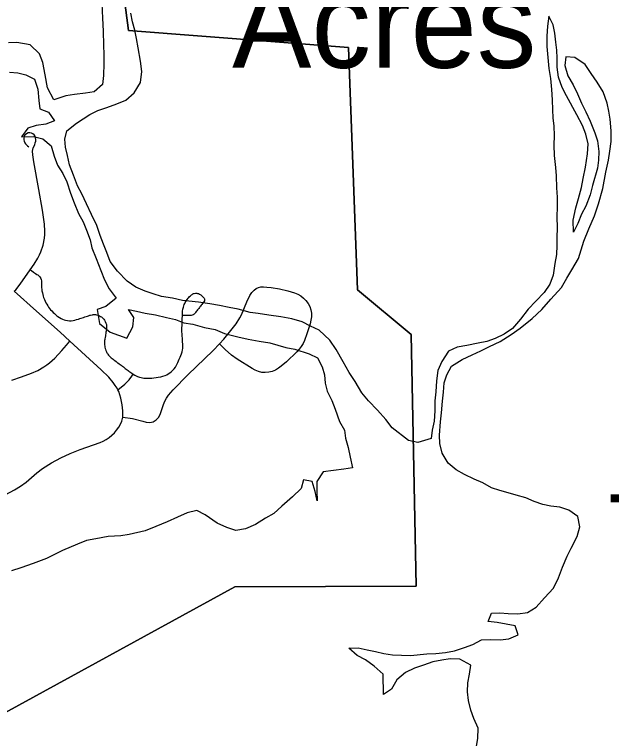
# Model space of a CAD drawing. Extents: x 63.4 to 97.4, y 0.4 to 22.4.
# Drawn here: x 68.856 to 69.385, y 18.029 to 18.671 of the extents above; entities that cross this region are included whole.
import ezdxf

# ---------------------------------------------------------------- set-up
doc = ezdxf.new("R2010")
doc.units = 0
for name, color, linetype in [('GM_X_County_Road', 7, 'Continuous'), ('GM_X_Minor_River', 7, 'Continuous'), ('GM_X_Township_Road', 7, 'Continuous'), ('GM_X_Township_Road_Text', 7, 'Continuous'), ('GM_X_Unincorporated_Text', 7, 'Continuous')]:
    doc.layers.add(name, color=color, linetype=linetype)

msp = doc.modelspace()

# ---------------------------------------------------------------- linework, layer by layer
at = {"layer": 'GM_X_County_Road'}
for points in [[(68.14823, 17.66929), (69.05133, 18.16366), (69.21209, 18.16431), (69.20756, 18.38738), (69.1601, 18.4272), (69.15215, 18.64192), (68.95685, 18.65711), (68.94039, 18.78359), (68.93181, 18.90191), (69.43522, 19.41404), (69.59166, 19.50401), (69.66099, 19.53265), (69.65817, 19.63452), (69.8362, 19.73783), (69.85096, 19.75421), (69.8604, 19.7797), (69.89905, 20.06449)], [(69.89905, 20.06449), (69.8604, 19.7797), (69.85096, 19.75421), (69.8362, 19.73783), (69.65817, 19.63452), (69.66099, 19.53265), (69.59166, 19.50401), (69.43522, 19.41404), (68.93181, 18.90191), (68.94039, 18.78359), (68.95685, 18.65711), (69.15215, 18.64192), (69.1601, 18.4272), (69.20756, 18.38738), (69.21209, 18.16431), (69.05133, 18.16366), (68.14823, 17.66929)]]:
    msp.add_lwpolyline(points, dxfattribs=at)
at = {"layer": 'GM_X_Minor_River'}
for points in [[(68.93307, 18.68111), (68.93389, 18.66819), (68.93433, 18.6564), (68.93477, 18.64424), (68.93482, 18.63587), (68.93486, 18.62789), (68.93453, 18.61724), (68.93381, 18.60925), (68.92626, 18.60275), (68.91867, 18.60158), (68.9088, 18.60039), (68.90122, 18.59921), (68.8906, 18.59574), (68.88485, 18.60636), (68.8829, 18.61776), (68.88094, 18.62877), (68.87787, 18.63636), (68.86947, 18.64431), (68.85769, 18.64653), (68.85048, 18.64612)], [(68.95439, 18.59528), (68.96195, 18.60178), (68.9676, 18.61093), (68.96868, 18.62083), (68.9675, 18.62994), (68.96554, 18.64172), (68.96398, 18.65008), (68.96242, 18.65729), (68.96048, 18.66489), (68.95893, 18.67249)], [(69.35725, 18.21702), (69.35568, 18.22614), (69.34768, 18.2318), (69.33969, 18.23443), (69.33172, 18.23515), (69.3245, 18.23664), (69.31689, 18.23926), (69.30928, 18.24265), (69.30092, 18.24489), (69.29369, 18.24713), (69.28647, 18.249), (69.27886, 18.25162), (69.27125, 18.25577), (69.26364, 18.25916), (69.25488, 18.2633), (69.24765, 18.26744), (69.2404, 18.27349), (69.23504, 18.28221), (69.2331, 18.29094), (69.23269, 18.29817), (69.23376, 18.30996), (69.23448, 18.31794), (69.23557, 18.32821), (69.23629, 18.3362), (69.237, 18.34457), (69.23924, 18.3518), (69.24338, 18.35942), (69.25284, 18.36517), (69.26193, 18.3694), (69.26951, 18.37285), (69.27708, 18.37669), (69.28655, 18.3813), (69.29639, 18.38743), (69.30433, 18.39317), (69.31492, 18.40158), (69.32361, 18.40961), (69.33154, 18.41877), (69.34098, 18.42908), (69.34587, 18.43747), (69.35039, 18.44471), (69.35603, 18.455), (69.36089, 18.47023), (69.36539, 18.48128), (69.37026, 18.49271), (69.37401, 18.50337), (69.37773, 18.51707), (69.38031, 18.53153), (69.38292, 18.54219), (69.38402, 18.55018), (69.38511, 18.55855), (69.38506, 18.56805), (69.38425, 18.57832), (69.38308, 18.58553), (69.38152, 18.59275), (69.37805, 18.60262), (69.37269, 18.61134), (69.36734, 18.61892), (69.36198, 18.62687), (69.35284, 18.6333), (69.34486, 18.63364), (69.34414, 18.62603), (69.34684, 18.61692), (69.35144, 18.60896), (69.35528, 18.60099), (69.35874, 18.59264), (69.36258, 18.58505), (69.36641, 18.57671), (69.37064, 18.56646), (69.37296, 18.55925), (69.37415, 18.54975), (69.37381, 18.54215), (69.37308, 18.53492), (69.36861, 18.51969), (69.36637, 18.51132), (69.36263, 18.50141), (69.35887, 18.49417), (69.35549, 18.48579), (69.35173, 18.47817), (69.3513, 18.48882), (69.3539, 18.49985), (69.35614, 18.50823), (69.35874, 18.51774), (69.36022, 18.52573), (69.36245, 18.53601), (69.36429, 18.5478), (69.36462, 18.55655), (69.36268, 18.56529), (69.3596, 18.57288), (69.35462, 18.58236), (69.34542, 18.59904), (69.34158, 18.60663), (69.3385, 18.61574), (69.33731, 18.62448), (69.33727, 18.63246), (69.33686, 18.63968), (69.33606, 18.6469), (69.33526, 18.65488), (69.3337, 18.6621), (69.32987, 18.66968), (69.32877, 18.66093), (69.32806, 18.65219)], [(69.32806, 18.65219), (69.32811, 18.64306), (69.32892, 18.63318), (69.32973, 18.6233), (69.33129, 18.61456), (69.3321, 18.60468), (69.33291, 18.59556), (69.33295, 18.58682), (69.33337, 18.57959), (69.33417, 18.57237), (69.33459, 18.56401), (69.33425, 18.55527), (69.33468, 18.54614), (69.33588, 18.53551), (69.33629, 18.52828), (69.33672, 18.51764), (69.33715, 18.50928), (69.33719, 18.50053), (69.33686, 18.49217), (69.33729, 18.48191), (69.33695, 18.47392), (69.33699, 18.46632), (69.33665, 18.45833), (69.33517, 18.45034), (69.33371, 18.44007), (69.33071, 18.43207), (69.32581, 18.42482), (69.31826, 18.41718), (69.31146, 18.40993), (69.30467, 18.40115), (69.2975, 18.39276), (69.29031, 18.38778), (69.28236, 18.38394), (69.27478, 18.38124), (69.2672, 18.37969), (69.25695, 18.37773), (69.24861, 18.37618), (69.24066, 18.37272), (69.23501, 18.36357), (69.23125, 18.35556), (69.23016, 18.34643), (69.22945, 18.33655), (69.22873, 18.32856), (69.22878, 18.31982), (69.22806, 18.31069), (69.22621, 18.3027), (69.22548, 18.29509), (69.21373, 18.29161), (69.20537, 18.29348), (69.19089, 18.30481), (69.18516, 18.31201), (69.1779, 18.32034), (69.16988, 18.32866), (69.16377, 18.33586), (69.15803, 18.34571), (69.15267, 18.35367), (69.14731, 18.36315), (69.14118, 18.37415), (69.13544, 18.38248), (69.1259, 18.39118), (69.11829, 18.39495), (69.11106, 18.39871), (69.10193, 18.40133), (69.09205, 18.40319), (69.08141, 18.40466), (69.07191, 18.40613), (69.0647, 18.40686), (69.05405, 18.40985), (69.04607, 18.41133), (69.03771, 18.41319), (69.02897, 18.41467), (69.01909, 18.41614), (69.00466, 18.4176), (68.99591, 18.41984), (68.98603, 18.42131), (68.97881, 18.42356), (68.97158, 18.4258), (68.96321, 18.42956), (68.95559, 18.43485), (68.94719, 18.44355), (68.9407, 18.45227), (68.93762, 18.46024), (68.93454, 18.46745), (68.93184, 18.47542), (68.92876, 18.48415), (68.92416, 18.49401), (68.91955, 18.50349), (68.91533, 18.51222), (68.9115, 18.51942), (68.90803, 18.52891), (68.90457, 18.53802), (68.90263, 18.54637), (68.90107, 18.55359), (68.90027, 18.56081), (68.90213, 18.56804), (68.91083, 18.57493), (68.92256, 18.58259), (68.92976, 18.58604), (68.93772, 18.58874), (68.94643, 18.5922), (68.95439, 18.59528)], [(68.85137, 18.62027), (68.85859, 18.61954), (68.86581, 18.61767), (68.87342, 18.61391), (68.87651, 18.60518), (68.87732, 18.59492), (68.87812, 18.5877), (68.88572, 18.58469), (68.89108, 18.57711), (68.8835, 18.57404), (68.87477, 18.57285), (68.86757, 18.57054), (68.86192, 18.56291), (68.87255, 18.56296), (68.88091, 18.5611), (68.88816, 18.55467), (68.89086, 18.54556), (68.89394, 18.53759), (68.89853, 18.53039), (68.90199, 18.5228), (68.90545, 18.51293), (68.90854, 18.5042), (68.91238, 18.49472), (68.9166, 18.48751), (68.91967, 18.47992), (68.92275, 18.47157), (68.92431, 18.46436), (68.92815, 18.45487), (68.93238, 18.44425), (68.93546, 18.4359), (68.93968, 18.42793), (68.9458, 18.4196), (68.93673, 18.41233), (68.92914, 18.40963), (68.93111, 18.3971), (68.94064, 18.38954), (68.94786, 18.38691), (68.95547, 18.38429), (68.96073, 18.3942), (68.96145, 18.40256), (68.95686, 18.40976), (68.96408, 18.40828), (68.97168, 18.40642), (68.9808, 18.40494), (68.99069, 18.4027), (68.99867, 18.40084), (69.0059, 18.39783), (69.01388, 18.39673), (69.02414, 18.39374), (69.03364, 18.39188), (69.04201, 18.3885), (69.0538, 18.38551), (69.06292, 18.38328), (69.0728, 18.38142), (69.0823, 18.37995), (69.09637, 18.37583), (69.10435, 18.37435), (69.11728, 18.37023), (69.12451, 18.36684), (69.12873, 18.35888), (69.13066, 18.35166), (69.13146, 18.34445), (69.13301, 18.33723), (69.13723, 18.32889), (69.14031, 18.3213), (69.14416, 18.31029), (69.14838, 18.30271), (69.14955, 18.29549), (69.15187, 18.28714)], [(69.15187, 18.28714), (69.15343, 18.27878), (69.15576, 18.26929), (69.14779, 18.26811), (69.12958, 18.26574), (69.12393, 18.25697), (69.12398, 18.24861), (69.1244, 18.23987), (69.12246, 18.24822), (69.11976, 18.25695), (69.11216, 18.25844), (69.10992, 18.25082), (69.10236, 18.24357), (69.09291, 18.23516), (69.08573, 18.22866), (69.07854, 18.22444), (69.06946, 18.21908), (69.06074, 18.21523), (69.05202, 18.21367), (69.04403, 18.2163), (69.03566, 18.22006), (69.02499, 18.22761), (69.01738, 18.23138), (69.00904, 18.22944), (69.00032, 18.22559), (68.99123, 18.22137), (68.98101, 18.21714), (68.97153, 18.21329), (68.9575, 18.21019), (68.94991, 18.20901), (68.93891, 18.20819), (68.92791, 18.20624), (68.91956, 18.20468), (68.91161, 18.2016), (68.89835, 18.19584), (68.88396, 18.18893), (68.87221, 18.18431), (68.86122, 18.18046), (68.85288, 18.17776)], [(69.15187, 18.28714), (69.15343, 18.27878), (69.15576, 18.26929), (69.14779, 18.26811), (69.12958, 18.26574), (69.12393, 18.25697), (69.12398, 18.24861), (69.1244, 18.23987), (69.12246, 18.24822), (69.11976, 18.25695), (69.11216, 18.25844), (69.10992, 18.25082), (69.10236, 18.24357), (69.09291, 18.23516), (69.08573, 18.22866), (69.07854, 18.22444), (69.06946, 18.21908), (69.06074, 18.21523), (69.05202, 18.21367), (69.04403, 18.2163), (69.03566, 18.22006), (69.02499, 18.22761), (69.01738, 18.23138), (69.00904, 18.22944), (69.00032, 18.22559), (68.99123, 18.22137), (68.98101, 18.21714), (68.97153, 18.21329), (68.9575, 18.21019), (68.94991, 18.20901), (68.93891, 18.20819), (68.92791, 18.20624), (68.91956, 18.20468), (68.91161, 18.2016), (68.89835, 18.19584), (68.88396, 18.18893), (68.87221, 18.18431), (68.86122, 18.18046), (68.85288, 18.17776)], [(69.26487, 18.01701), (69.26671, 18.02918), (69.26704, 18.03831), (69.2632, 18.04703), (69.26051, 18.05424), (69.25856, 18.06298), (69.25777, 18.07057), (69.2581, 18.07856), (69.25958, 18.08617), (69.26068, 18.09416), (69.25078, 18.09943), (69.24243, 18.09977), (69.23484, 18.09859), (69.22688, 18.09704), (69.21854, 18.09434), (69.21058, 18.09164), (69.20263, 18.0878), (69.19507, 18.0813), (69.19018, 18.07291), (69.18298, 18.06832), (69.18289, 18.08618), (69.17488, 18.09337), (69.16726, 18.09904), (69.15965, 18.1028), (69.1524, 18.10923), (69.16075, 18.10965), (69.16873, 18.10778), (69.17596, 18.1063), (69.18356, 18.10444), (69.19116, 18.10333), (69.19913, 18.10299), (69.20711, 18.10265), (69.22153, 18.10423), (69.2295, 18.10465), (69.23823, 18.10545), (69.24619, 18.10701), (69.25491, 18.10972), (69.26249, 18.11241), (69.27006, 18.11663), (69.27765, 18.11705), (69.28677, 18.11671), (69.29435, 18.11751), (69.30269, 18.12097), (69.29999, 18.12894), (69.29201, 18.13042), (69.28403, 18.1319), (69.27605, 18.133), (69.27905, 18.14024), (69.28626, 18.14066), (69.29386, 18.13993), (69.30221, 18.13959), (69.31094, 18.14077), (69.31851, 18.14575), (69.32606, 18.15377), (69.33399, 18.16255), (69.33849, 18.17169), (69.34186, 18.18121), (69.34599, 18.19074), (69.34975, 18.19798), (69.35501, 18.20827), (69.35725, 18.21702)]]:
    msp.add_lwpolyline(points, dxfattribs=at)
at = {"layer": 'GM_X_Township_Road'}
for points in [[(68.86969, 18.44482), (68.87327, 18.44994), (68.87653, 18.45525), (68.87793, 18.45803), (68.87916, 18.4609), (68.88105, 18.46684), (68.88225, 18.47296), (68.88259, 18.47606), (68.88272, 18.47917), (68.88243, 18.48539), (68.88061, 18.49774), (68.87738, 18.51617), (68.87275, 18.54075), (68.87183, 18.54688), (68.87171, 18.54995), (68.87191, 18.55147), (68.87228, 18.55294), (68.87362, 18.55581), (68.87412, 18.55735), (68.87452, 18.55883), (68.87465, 18.56045), (68.87442, 18.56184), (68.87394, 18.56324), (68.87313, 18.56444), (68.8719, 18.56557), (68.87078, 18.56608), (68.8692, 18.56632), (68.86776, 18.56622), (68.86625, 18.56557), (68.86513, 18.5647), (68.86454, 18.5639), (68.86421, 18.56303), (68.86387, 18.56145), (68.86392, 18.56024), (68.86421, 18.55887), (68.86483, 18.55762), (68.86541, 18.55666), (68.86649, 18.55552), (68.86733, 18.55479), (68.86853, 18.55405)], [(68.8555, 18.42586), (68.85682, 18.42721), (68.86075, 18.43205), (68.86969, 18.44482)], [(68.86969, 18.44482), (68.87073, 18.4441), (68.87257, 18.44281), (68.87421, 18.44171), (68.87562, 18.44076), (68.87629, 18.4403), (68.87696, 18.43982), (68.87763, 18.43912), (68.87813, 18.43856), (68.87895, 18.43715), (68.8793, 18.43632), (68.87958, 18.43518), (68.87967, 18.43429), (68.87964, 18.43323), (68.87959, 18.43225), (68.87962, 18.43082), (68.87968, 18.4292), (68.87989, 18.42738), (68.88002, 18.4263), (68.88042, 18.42431), (68.88074, 18.42295), (68.88112, 18.4216), (68.88153, 18.42028), (68.88223, 18.41846), (68.8829, 18.41697), (68.88363, 18.41552), (68.88425, 18.4145), (68.88517, 18.41286), (68.88588, 18.41185), (68.88679, 18.41065), (68.88766, 18.4095), (68.88868, 18.40839), (68.88996, 18.40706), (68.89109, 18.40599), (68.89215, 18.4051), (68.89336, 18.40413), (68.89427, 18.40347), (68.89566, 18.40253), (68.89703, 18.40174), (68.89824, 18.40115), (68.89973, 18.40056), (68.90109, 18.40017), (68.90264, 18.39987), (68.90435, 18.39974), (68.90604, 18.39969), (68.90762, 18.39987), (68.90926, 18.40016), (68.91084, 18.40064), (68.9124, 18.40115), (68.91374, 18.40157), (68.91486, 18.40196), (68.91681, 18.40261), (68.91807, 18.40301), (68.91922, 18.40343), (68.92053, 18.40385), (68.92131, 18.4041), (68.92246, 18.40449), (68.92317, 18.4047), (68.92481, 18.40505), (68.92558, 18.40514), (68.92637, 18.40517), (68.92753, 18.40509), (68.92856, 18.40492), (68.92996, 18.40454), (68.93101, 18.40411), (68.93212, 18.4035), (68.93287, 18.40301), (68.93353, 18.40249), (68.93427, 18.40181), (68.9349, 18.40115), (68.93561, 18.4001), (68.93627, 18.39901), (68.93688, 18.39747), (68.9372, 18.39629), (68.93732, 18.39556), (68.93742, 18.39481), (68.93745, 18.39402), (68.93746, 18.39322), (68.93734, 18.39239), (68.93718, 18.39127), (68.93688, 18.38967), (68.93668, 18.3883), (68.9365, 18.38726), (68.93635, 18.3863), (68.93611, 18.38495), (68.93591, 18.38378), (68.93578, 18.38296), (68.93568, 18.38221), (68.93557, 18.3812), (68.93552, 18.3803), (68.93552, 18.37965), (68.93557, 18.37843), (68.93573, 18.37719), (68.93591, 18.37617), (68.93617, 18.37512), (68.93641, 18.37435), (68.9368, 18.37333), (68.93705, 18.37274), (68.93739, 18.372), (68.93772, 18.37133), (68.93823, 18.37051), (68.93864, 18.37), (68.93924, 18.36912), (68.93971, 18.36856), (68.94028, 18.36798), (68.94093, 18.36728), (68.94151, 18.3668), (68.94229, 18.36615), (68.94313, 18.36549), (68.94371, 18.36511), (68.94464, 18.3644), (68.94579, 18.36357), (68.94691, 18.36271), (68.94748, 18.3623), (68.9485, 18.36152), (68.94942, 18.36084), (68.95023, 18.36022), (68.9509, 18.35974), (68.95159, 18.35925), (68.95237, 18.35866), (68.95304, 18.35817), (68.95398, 18.35744), (68.95483, 18.35685), (68.95576, 18.35617), (68.95669, 18.35546), (68.95728, 18.35498), (68.95815, 18.35437), (68.95883, 18.35384), (68.95987, 18.35309), (68.96107, 18.35224)], [(68.90488, 18.38164), (68.89613, 18.38965), (68.87531, 18.4082), (68.8555, 18.42586)], [(69.03746, 18.37909), (69.0413, 18.38341), (69.04659, 18.3895), (69.05229, 18.39691), (69.05568, 18.40212), (69.05708, 18.40491), (69.06189, 18.41643), (69.06451, 18.42204), (69.06618, 18.42463), (69.06823, 18.42684), (69.07001, 18.42827), (69.07208, 18.42911), (69.07416, 18.42967), (69.0765, 18.42983), (69.07971, 18.42953), (69.08355, 18.42903), (69.09088, 18.42785), (69.09827, 18.42629), (69.10426, 18.42454), (69.10711, 18.4233), (69.10977, 18.42173), (69.11219, 18.41979), (69.11432, 18.41751), (69.11615, 18.41497), (69.11763, 18.41223), (69.11867, 18.40931), (69.11917, 18.40626), (69.11913, 18.40317), (69.11864, 18.4001), (69.11791, 18.39705), (69.11524, 18.38808), (69.11311, 18.38224), (69.11174, 18.37945), (69.11008, 18.37683), (69.10816, 18.37438), (69.10609, 18.37205), (69.09718, 18.36331), (69.09244, 18.35927), (69.08989, 18.35748), (69.08719, 18.35592), (69.08432, 18.35472), (69.08131, 18.35395), (69.07822, 18.35365), (69.07513, 18.35387), (69.07212, 18.35461), (69.06923, 18.35575), (69.06647, 18.35722), (69.05325, 18.36549), (69.04828, 18.36923), (69.04265, 18.37427), (69.03746, 18.37909)], [(69.00467, 18.40438), (69.00472, 18.40605), (69.00484, 18.40812), (69.00516, 18.41003), (69.00554, 18.41169), (69.00594, 18.41302), (69.00633, 18.41405), (69.00669, 18.4149), (69.00715, 18.41579), (69.00766, 18.41678), (69.00824, 18.41769), (69.00889, 18.41863), (69.00965, 18.41959), (69.01029, 18.42037), (69.01098, 18.42108), (69.01184, 18.42186), (69.01264, 18.42259), (69.01332, 18.42306), (69.01395, 18.42342), (69.01461, 18.42371), (69.01526, 18.42391), (69.01626, 18.42407), (69.01741, 18.42403), (69.01813, 18.42391), (69.01886, 18.4237), (69.01976, 18.42334), (69.02036, 18.42297), (69.02089, 18.42255), (69.02151, 18.42201), (69.02241, 18.42116), (69.02297, 18.42063), (69.02343, 18.42018), (69.02386, 18.41968), (69.02415, 18.41912), (69.02431, 18.41818), (69.02414, 18.41728), (69.0237, 18.41654), (69.0231, 18.41574), (69.02251, 18.41497), (69.02195, 18.41423), (69.02134, 18.41344), (69.02066, 18.41255), (69.02025, 18.41203), (69.01972, 18.41132), (69.0192, 18.41066), (69.01871, 18.41001), (69.01818, 18.40932), (69.01757, 18.40852), (69.01698, 18.40774), (69.01636, 18.40691), (69.0159, 18.40633), (69.01519, 18.40555), (69.01466, 18.40514), (69.01411, 18.40484), (69.01333, 18.40456), (69.0126, 18.40443), (69.01182, 18.40444), (69.01078, 18.40442), (69.00989, 18.40441), (69.00883, 18.40441), (69.00798, 18.4044), (69.00668, 18.40437), (69.00543, 18.40437), (69.00467, 18.40438)], [(68.96107, 18.35224), (68.96244, 18.35144), (68.96371, 18.35085), (68.96498, 18.35025), (68.96649, 18.34972), (68.96802, 18.34924), (68.97047, 18.34881), (68.97233, 18.34865), (68.97387, 18.34862), (68.97529, 18.34865), (68.97758, 18.34881), (68.97942, 18.34904), (68.9813, 18.34932), (68.98322, 18.34954), (68.98552, 18.35), (68.98739, 18.35039), (68.98941, 18.35101), (68.99094, 18.35178), (68.99214, 18.35253), (68.99365, 18.35345), (68.99508, 18.35468), (68.99652, 18.356), (68.99744, 18.3571), (68.99846, 18.35861), (68.9993, 18.36014), (69, 18.36142), (69.00064, 18.3627), (69.00133, 18.36421), (69.00192, 18.36547), (69.00269, 18.36725), (69.00338, 18.36885), (69.00395, 18.37036), (69.00449, 18.37218), (69.00482, 18.37374), (69.00499, 18.37499), (69.00508, 18.37646), (69.00497, 18.37841), (69.0048, 18.3815), (69.0047, 18.38398), (69.00454, 18.38619), (69.00441, 18.38796), (69.0043, 18.38984), (69.0043, 18.39312), (69.00439, 18.3957), (69.00456, 18.39854), (69.00454, 18.40001), (69.00451, 18.40104), (69.00467, 18.40438)], [(68.85323, 18.34702), (68.86202, 18.35), (68.87075, 18.35314), (68.87639, 18.35569), (68.88179, 18.3587), (68.88435, 18.36043), (68.8868, 18.36232), (68.8914, 18.36645), (68.89781, 18.37317), (68.90177, 18.37792), (68.90488, 18.38164)], [(68.94746, 18.33833), (68.94674, 18.33974), (68.94512, 18.34236), (68.9433, 18.34487), (68.93927, 18.34958), (68.93268, 18.35615), (68.90488, 18.38164)], [(68.95186, 18.31405), (68.96039, 18.31299), (68.96952, 18.31048), (68.9726, 18.30982), (68.97567, 18.30956), (68.9787, 18.31008), (68.98138, 18.31165), (68.98347, 18.31392), (68.98495, 18.31663), (68.98784, 18.32553), (68.98911, 18.32837), (68.99064, 18.33107), (68.99243, 18.33361), (68.99649, 18.33833), (69.00955, 18.3517), (69.03197, 18.37335), (69.03746, 18.37909)], [(68.94746, 18.33833), (68.95365, 18.34333), (68.95538, 18.34519), (68.9573, 18.34721), (68.95979, 18.35052), (68.96107, 18.35224)], [(68.95186, 18.31405), (68.95174, 18.3199), (68.95134, 18.32505), (68.95016, 18.33114), (68.94927, 18.3341), (68.94814, 18.33698), (68.94746, 18.33833)], [(68.84745, 18.24533), (68.85573, 18.24972), (68.86106, 18.25297), (68.86612, 18.2566), (68.87565, 18.26468), (68.88056, 18.26853), (68.88847, 18.27352), (68.89667, 18.27805), (68.90515, 18.28204), (68.91386, 18.28548), (68.93159, 18.29157), (68.93444, 18.29283), (68.93717, 18.29432), (68.93973, 18.29609), (68.94211, 18.29811), (68.94432, 18.30032), (68.94633, 18.3027), (68.94818, 18.30522), (68.94987, 18.30787), (68.95104, 18.31055), (68.95186, 18.31405)]]:
    msp.add_lwpolyline(points, dxfattribs=at)

# ---------------------------------------------------------------- texts
at = {"layer": 'GM_X_Township_Road_Text'}
msp.add_text('T', height=0.05682, rotation=271.26009, dxfattribs=at).set_placement((69.38425, 18.26524))
at = {"layer": 'GM_X_Unincorporated_Text'}
msp.add_text('Acres', height=0.078977, rotation=0.00001, dxfattribs=at).set_placement((69.04877, 18.62404))

doc.saveas('drawing.dxf')
